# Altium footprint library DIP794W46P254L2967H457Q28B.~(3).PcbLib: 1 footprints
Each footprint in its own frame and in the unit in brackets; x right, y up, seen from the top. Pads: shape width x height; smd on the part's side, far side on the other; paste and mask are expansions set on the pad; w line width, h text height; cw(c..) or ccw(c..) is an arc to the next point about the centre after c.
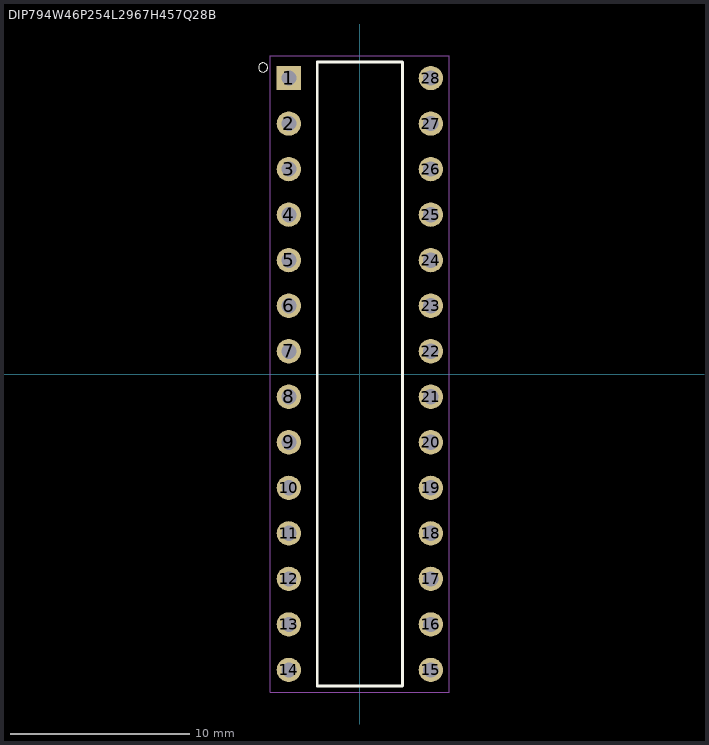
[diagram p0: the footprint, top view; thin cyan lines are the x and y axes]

## DIP794W46P254L2967H457Q28B [mm]
pads (28):
  rect 1.358x1.358 hole 0.85: 1(-3.96,16.51)
  round 1.358 hole 0.85: 2(-3.96,13.97) 3(-3.96,11.43) 4(-3.96,8.89) 5(-3.96,6.35) 6(-3.96,3.81) 7(-3.96,1.27) 8(-3.96,-1.27) 9(-3.96,-3.81) 10(-3.96,-6.35) 11(-3.96,-8.89) 12(-3.96,-11.43) 13(-3.96,-13.97) 14(-3.96,-16.51) 15(3.96,-16.51) 16(3.96,-13.97) 17(3.96,-11.43) 18(3.96,-8.89) 19(3.96,-6.35) 20(3.96,-3.81) 21(3.96,-1.27) 22(3.96,1.27) 23(3.96,3.81) 24(3.96,6.35) 25(3.96,8.89) 26(3.96,11.43) 27(3.96,13.97) 28(3.96,16.51)
Top Overlay:
  circle w0: c-5.4,17.1 r0.254
  lines w0.152: -2.38,-17.4 -2.38,17.4 2.38,17.4 2.38,-17.4 -2.38,-17.4
Mechanical 15:
  lines w0.05: -5,-17.75 5,-17.75 5,17.75 -5,17.75 -5,-17.75
3D body "ATMEGA328P-PN--3DModel-STEP-1.STEP": height 4.57, standoff -3.43, extent -5.08,-17.335 5.08,17.336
